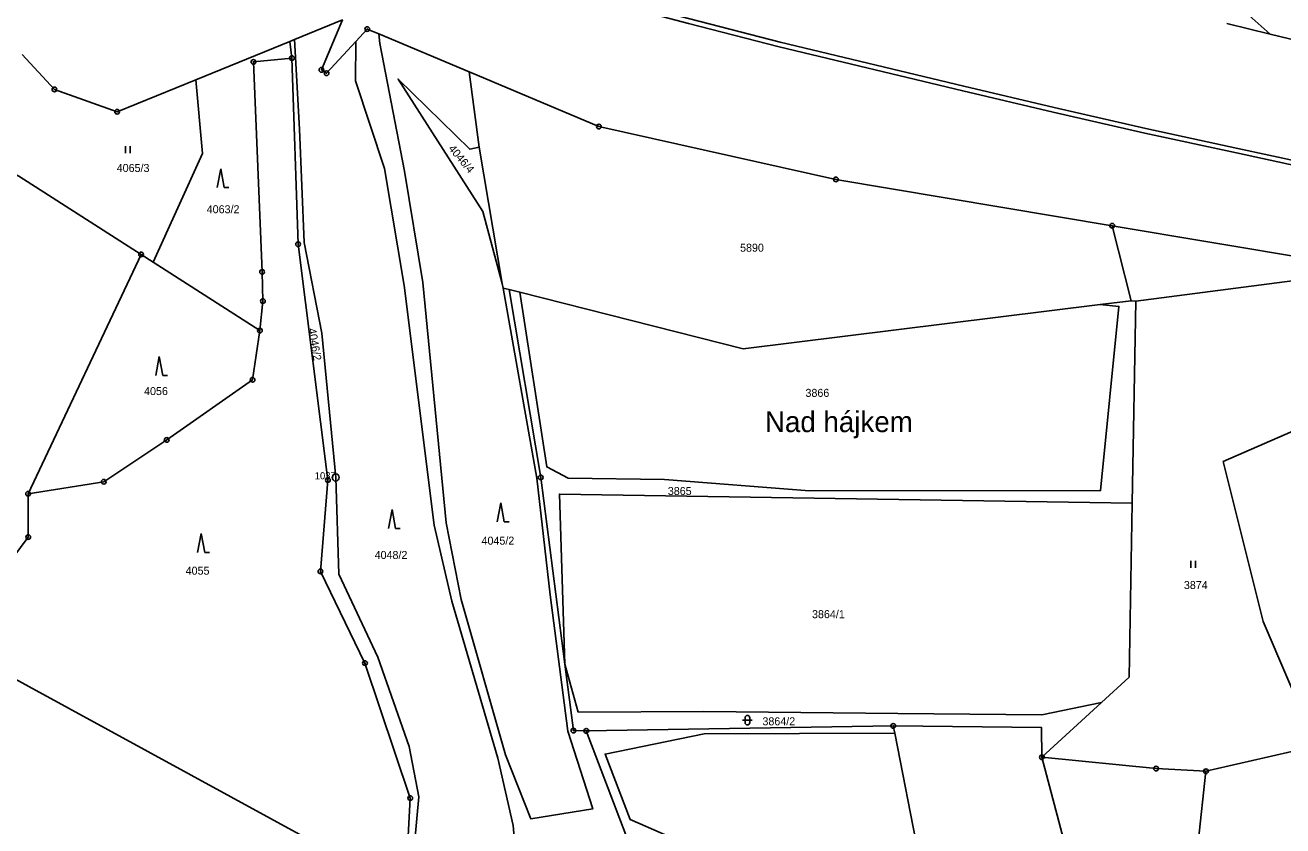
# Model space of a CAD drawing. Extents: x -644096 to -634268, y -1141430 to -1133463.
# Drawn here: x -640398.2 to -640131.1, y -1137371.3 to -1137201.2 of the extents above; entities that cross this region are included whole.
import ezdxf

# ---------------------------------------------------------------- set-up
doc = ezdxf.new("R2010")
doc.units = 0
for name, color, linetype in [('_CIVIL_CONSTRUCTION', 7, 'Continuous'), ('B_Hranice _3D', 7, 'Continuous'), ('svrsek_osa_sjezdy', 7, 'Continuous'), ('svrsek_osa_VRT', 7, 'Continuous'), ('svrsek_popisy_VRT', 7, 'Continuous'), ('terminal_VRT', 7, 'Continuous')]:
    doc.layers.add(name, color=color, linetype=linetype)

msp = doc.modelspace()

# ---------------------------------------------------------------- linework, layer by layer
at = {"layer": '_CIVIL_CONSTRUCTION'}
for centre, radius in [((-640325.54, -1137202.04), 0.5), ((-640325.54, -1137202.04), 0.0303), ((-640341.55, -1137208.21), 0.5), ((-640349.72, -1137209.02), 0.5), ((-640349.72, -1137209.02), 0.0303), ((-640341.55, -1137208.21), 0.0303), ((-640335.26, -1137210.7), 0.5), ((-640335.26, -1137210.7), 0.0303), ((-640334.18, -1137211.42), 0.5), ((-640334.18, -1137211.42), 0.0303), ((-640391.96, -1137214.86), 0.5), ((-640391.96, -1137214.86), 0.0303), ((-640378.66, -1137219.61), 0.5), ((-640378.66, -1137219.61), 0.0303), ((-640276.35, -1137222.74), 0.5), ((-640276.35, -1137222.74), 0.0303), ((-640226.01, -1137233.97), 0.5), ((-640226.01, -1137233.97), 0.0303), ((-640167.33, -1137243.83), 0.5), ((-640167.33, -1137243.83), 0.0303), ((-640340.22, -1137247.74), 0.5), ((-640340.22, -1137247.74), 0.0303), ((-640373.56, -1137249.93), 0.5), ((-640373.56, -1137249.93), 0.0303), ((-640347.86, -1137253.64), 0.5), ((-640347.86, -1137253.64), 0.0303), ((-640347.7, -1137259.83), 0.5), ((-640347.7, -1137259.83), 0.0303), ((-640348.34, -1137266.11), 0.5), ((-640348.34, -1137266.11), 0.0303), ((-640349.88, -1137276.55), 0.5), ((-640349.88, -1137276.55), 0.0303), ((-640368.13, -1137289.34), 0.5), ((-640368.13, -1137289.34), 0.0303), ((-640381.48, -1137298.23), 0.5), ((-640381.48, -1137298.23), 0.0303), ((-640333.9, -1137297.85), 0.5), ((-640333.9, -1137297.85), 0.0303), ((-640332.24, -1137297.31), 0.75), ((-640332.24, -1137297.31), 0.03), ((-640288.71, -1137297.3), 0.5), ((-640288.71, -1137297.3), 0.0303), ((-640397.57, -1137300.77), 0.5), ((-640397.57, -1137300.77), 0.0303), ((-640397.53, -1137309.97), 0.5), ((-640397.53, -1137309.97), 0.0303), ((-640335.48, -1137317.25), 0.5), ((-640335.48, -1137317.25), 0.0303), ((-640326.02, -1137336.73), 0.5), ((-640326.02, -1137336.73), 0.0303), ((-640281.76, -1137351.09), 0.5), ((-640281.76, -1137351.09), 0.0303), ((-640279.02, -1137351.14), 0.5), ((-640279.02, -1137351.14), 0.0303), ((-640213.83, -1137350.09), 0.5), ((-640213.83, -1137350.09), 0.0303), ((-640182.26, -1137356.75), 0.5), ((-640182.26, -1137356.75), 0.0303), ((-640158.04, -1137359.15), 0.5), ((-640158.04, -1137359.15), 0.0303), ((-640147.43, -1137359.74), 0.5), ((-640147.43, -1137359.74), 0.0303), ((-640316.4, -1137365.43), 0.5), ((-640316.4, -1137365.43), 0.0303)]:
    msp.add_circle(centre, radius, dxfattribs=at)
at = {"layer": 'B_Hranice _3D'}
for points in [[(-640410.95, -1137156.75), (-640392.05, -1137162.55), (-640372.94, -1137168.36), (-640353.83, -1137174.19), (-640334.69, -1137179.7), (-640315.68, -1137185.12), (-640296.09, -1137190.56), (-640276.72, -1137195.7), (-640257.32, -1137200.83), (-640238.07, -1137205.8), (-640199.1, -1137215.17), (-640179.88, -1137219.7), (-640160.4, -1137224.13), (-640140.92, -1137228.36), (-640121.14, -1137232.64), (-640101.68, -1137236.69), (-640081.8, -1137240.67), (-640062.49, -1137244.41), (-640042.82, -1137248.24), (-640022.97, -1137252), (-640003.54, -1137255.62), (-639984.08, -1137259.27), (-639964.57, -1137262.92), (-639943.41, -1137266.9)], [(-639943.23, -1137265.92), (-639964.39, -1137261.94), (-639983.9, -1137258.29), (-640003.36, -1137254.64), (-640022.79, -1137251.02), (-640042.64, -1137247.26), (-640062.29, -1137243.43), (-640081.6, -1137239.69), (-640101.48, -1137235.71), (-640120.94, -1137231.66), (-640140.7, -1137227.38), (-640160.18, -1137223.15), (-640179.66, -1137218.72), (-640198.86, -1137214.19), (-640237.83, -1137204.82), (-640257.06, -1137199.87), (-640276.46, -1137194.74), (-640295.83, -1137189.6), (-640315.4, -1137184.16), (-640334.41, -1137178.74), (-640353.55, -1137173.23), (-640372.64, -1137167.4), (-640391.75, -1137161.59), (-640410.65, -1137155.79)]]:
    msp.add_lwpolyline(points, dxfattribs=at)
at = {"layer": 'svrsek_osa_sjezdy'}
for p, q in [((-640376.86, -1137228.42), (-640376.86, -1137226.92)), ((-640375.86, -1137228.42), (-640375.86, -1137226.92)), ((-640356.65, -1137231.72), (-640357.4, -1137235.72)), ((-640355.9, -1137235.72), (-640356.65, -1137231.72)), ((-640355.9, -1137235.72), (-640354.9, -1137235.72)), ((-640369.72, -1137271.63), (-640370.47, -1137275.63)), ((-640368.97, -1137275.63), (-640369.72, -1137271.63)), ((-640368.97, -1137275.63), (-640367.97, -1137275.63)), ((-640320.28, -1137304.13), (-640321.03, -1137308.13)), ((-640319.53, -1137308.13), (-640320.28, -1137304.13)), ((-640297.18, -1137302.72), (-640297.93, -1137306.72)), ((-640296.43, -1137306.72), (-640297.18, -1137302.72)), ((-640296.43, -1137306.72), (-640295.43, -1137306.72)), ((-640360.81, -1137309.22), (-640361.56, -1137313.22)), ((-640360.06, -1137313.22), (-640360.81, -1137309.22)), ((-640319.53, -1137308.13), (-640318.53, -1137308.13)), ((-640360.06, -1137313.22), (-640359.06, -1137313.22)), ((-640150.66, -1137316.53), (-640150.66, -1137315.03)), ((-640149.66, -1137316.53), (-640149.66, -1137315.03)), ((-640245.82, -1137348.87), (-640243.82, -1137348.87)), ((-640245.32, -1137348.37), (-640245.32, -1137349.37)), ((-640244.32, -1137349.37), (-640244.32, -1137348.37))]:
    msp.add_line(p, q, dxfattribs=at)
for centre, start, end in [((-640244.82, -1137348.37), 0, 180), ((-640244.82, -1137349.37), 180, 359.9879)]:
    msp.add_arc(centre, 0.5, start, end, dxfattribs=at)
at = {"layer": 'terminal_VRT'}
for p, q in [((-640145.68, -1137192.52), (-640133.78, -1137203.1)), ((-640142.98, -1137200.87), (-640133.78, -1137203.1)), ((-640341.98, -1137204.66), (-640361.94, -1137212.8)), ((-640341.02, -1137204.27), (-640341.98, -1137204.66)), ((-640341.98, -1137204.66), (-640341.55, -1137208.21)), ((-640303.89, -1137211.11), (-640323.06, -1137203.08)), ((-640301.8, -1137227.14), (-640303.89, -1137211.11)), ((-640296.86, -1137256.12), (-640301.8, -1137227.14)), ((-640163.31, -1137259.75), (-640167.33, -1137243.83)), ((-640081.05, -1137258.36), (-640167.33, -1137243.83)), ((-640373.56, -1137249.93), (-640397.57, -1137300.77)), ((-640371.03, -1137251.57), (-640373.56, -1137249.93)), ((-640348.34, -1137266.11), (-640371.03, -1137251.57)), ((-640126.94, -1137255.24), (-640162.32, -1137259.87)), ((-640296.71, -1137257.07), (-640296.86, -1137256.12)), ((-640295.43, -1137257.39), (-640296.71, -1137257.07)), ((-640293.14, -1137257.97), (-640295.43, -1137257.39)), ((-640163.31, -1137259.75), (-640169.89, -1137260.57)), ((-640162.32, -1137259.87), (-640163.31, -1137259.75)), ((-640163.09, -1137302.75), (-640162.32, -1137259.87)), ((-640182.26, -1137356.75), (-640169.63, -1137345.13)), ((-640213.83, -1137350.09), (-640279.02, -1137351.14)), ((-640213.52, -1137351.66), (-640213.83, -1137350.09)), ((-640201.53, -1137413.13), (-640213.52, -1137351.66)), ((-640147.43, -1137359.74), (-640125.16, -1137354.6))]:
    msp.add_line(p, q, dxfattribs=at)
for points in [[(-640327.95, -1137204.66), (-640334.18, -1137211.42), (-640335.26, -1137210.7), (-640330.83, -1137200.11), (-640341.02, -1137204.27)], [(-640323.06, -1137203.08), (-640325.54, -1137202.04), (-640327.95, -1137204.66)], [(-640316.67, -1137354.45), (-640323.27, -1137335.45), (-640331.59, -1137317.82), (-640332.24, -1137297.31), (-640335.19, -1137266.63), (-640338.97, -1137247.36), (-640339.91, -1137223.29), (-640341.02, -1137204.27)], [(-640327.95, -1137204.66), (-640328.04, -1137213.02), (-640321.85, -1137231.65), (-640317.71, -1137256.53), (-640311.32, -1137307.43), (-640307.58, -1137323.59), (-640297.83, -1137356.91), (-640294.54, -1137371.27), (-640293.98, -1137377.99), (-640289.12, -1137400.84), (-640318.78, -1137398.87)], [(-640323.06, -1137203.08), (-640322.85, -1137205.13), (-640317.64, -1137232.25), (-640313.76, -1137255.88), (-640308.77, -1137306.94), (-640305.62, -1137323.21), (-640296.15, -1137356.25), (-640290.82, -1137369.81), (-640277.65, -1137367.74), (-640282.95, -1137351.24), (-640286.7, -1137322.24), (-640289.5, -1137297.43), (-640296.71, -1137257.07)], [(-640133.78, -1137203.1), (-640109.2, -1137209.07), (-640076.53, -1137209.74)], [(-640361.94, -1137212.8), (-640378.66, -1137219.61), (-640391.96, -1137214.86), (-640398.83, -1137207.43)], [(-640341.55, -1137208.21), (-640349.72, -1137209.02), (-640347.86, -1137253.64), (-640347.7, -1137259.83), (-640348.34, -1137266.11)], [(-640341.55, -1137208.21), (-640340.22, -1137247.74), (-640333.9, -1137297.85), (-640335.48, -1137317.25), (-640326.02, -1137336.73), (-640316.4, -1137365.43), (-640317.48, -1137385.68)], [(-640361.94, -1137212.8), (-640360.54, -1137228.5), (-640371.03, -1137251.57)], [(-640296.86, -1137256.12), (-640300.96, -1137240.78), (-640319, -1137212.65), (-640303.76, -1137227.58), (-640301.8, -1137227.14)], [(-640167.33, -1137243.83), (-640226.01, -1137233.97), (-640276.35, -1137222.74), (-640303.54, -1137211.26), (-640303.89, -1137211.11)], [(-640373.56, -1137249.93), (-640399.54, -1137233.32), (-640402.93, -1137231.48)], [(-640295.43, -1137257.39), (-640288.71, -1137297.3), (-640283.59, -1137336.95)], [(-640169.89, -1137260.57), (-640165.92, -1137260.97), (-640169.82, -1137300.08), (-640231.6, -1137300.15), (-640262.4, -1137297.74), (-640282.86, -1137297.44), (-640287.41, -1137295.05), (-640293.14, -1137257.97)], [(-640169.89, -1137260.57), (-640245.68, -1137269.97), (-640293.14, -1137257.97)], [(-640348.34, -1137266.11), (-640349.88, -1137276.55), (-640368.13, -1137289.34), (-640381.48, -1137298.23), (-640397.57, -1137300.77)], [(-640118.35, -1137282.62), (-640126.26, -1137286.29), (-640143.76, -1137293.93), (-640135.31, -1137327.88), (-640125.01, -1137351.95), (-640125.16, -1137354.6)], [(-640397.57, -1137300.77), (-640397.53, -1137309.97), (-640406.95, -1137322.62)], [(-640163.09, -1137302.75), (-640284.73, -1137300.82), (-640283.59, -1137336.95)], [(-640169.63, -1137345.13), (-640163.75, -1137339.72), (-640163.09, -1137302.75)], [(-640317.48, -1137385.68), (-640320.79, -1137383.58), (-640414.33, -1137332.53)], [(-640283.59, -1137336.95), (-640280.75, -1137347.17), (-640254.05, -1137347.03), (-640212.87, -1137347.47), (-640182.29, -1137347.75), (-640169.63, -1137345.13)], [(-640283.59, -1137336.95), (-640281.76, -1137351.09), (-640279.02, -1137351.14)], [(-640279.02, -1137351.14), (-640270.63, -1137373.26), (-640266.26, -1137398.59), (-640265.38, -1137407.59)], [(-640213.52, -1137351.66), (-640253.98, -1137351.74), (-640275.02, -1137356.06), (-640269.73, -1137369.99), (-640267.58, -1137370.9), (-640255.99, -1137376), (-640268.44, -1137383), (-640265.38, -1137398.44), (-640263.43, -1137407.76)], [(-640182.26, -1137356.75), (-640182.35, -1137350.45), (-640213.83, -1137350.09)], [(-640316.49, -1137385.92), (-640314.58, -1137365.18), (-640316.67, -1137354.45)], [(-640198.71, -1137427.44), (-640197.51, -1137413.46), (-640191.55, -1137408.23), (-640185.88, -1137388.6), (-640176.73, -1137377.92), (-640182.26, -1137356.75)], [(-640182.26, -1137356.75), (-640158.04, -1137359.15), (-640147.43, -1137359.74)], [(-640147.43, -1137359.74), (-640150.71, -1137390.05), (-640168.05, -1137408.9), (-640173.09, -1137426.45), (-640177.18, -1137442)]]:
    msp.add_lwpolyline(points, dxfattribs=at)

# ---------------------------------------------------------------- texts
at = {"layer": '_CIVIL_CONSTRUCTION'}
msp.add_text('1037', height=1.5, dxfattribs=at).set_placement((-640336.69, -1137297.69))
at = {"layer": 'svrsek_osa_VRT'}
for s, rotation, p in [('4046/4', 310, (-640308.42, -1137227.49)), ('4046/2', 280, (-640338.11, -1137265.75))]:
    msp.add_text(s, height=1.7, rotation=rotation, dxfattribs=at).set_placement(p)
for s, p in [('4065/3', (-640378.74, -1137232.4)), ('4063/2', (-640359.63, -1137241.17)), ('5890', (-640246.37, -1137249.34)), ('4056', (-640372.93, -1137279.8)), ('3866', (-640232.48, -1137280.18)), ('3865', (-640261.71, -1137301.03)), ('4045/2', (-640301.27, -1137311.58)), ('4048/2', (-640323.97, -1137314.62)), ('4055', (-640364.1, -1137317.96)), ('3874', (-640152.12, -1137321.01)), ('3864/1', (-640231.09, -1137327.2)), ('3864/2', (-640241.62, -1137349.96))]:
    msp.add_text(s, height=1.7, dxfattribs=at).set_placement(p)
at = {"layer": 'svrsek_popisy_VRT'}
msp.add_text('Nad hájkem', height=4.4, dxfattribs=at).set_placement((-640241.09, -1137287.67))

doc.saveas('drawing.dxf')
